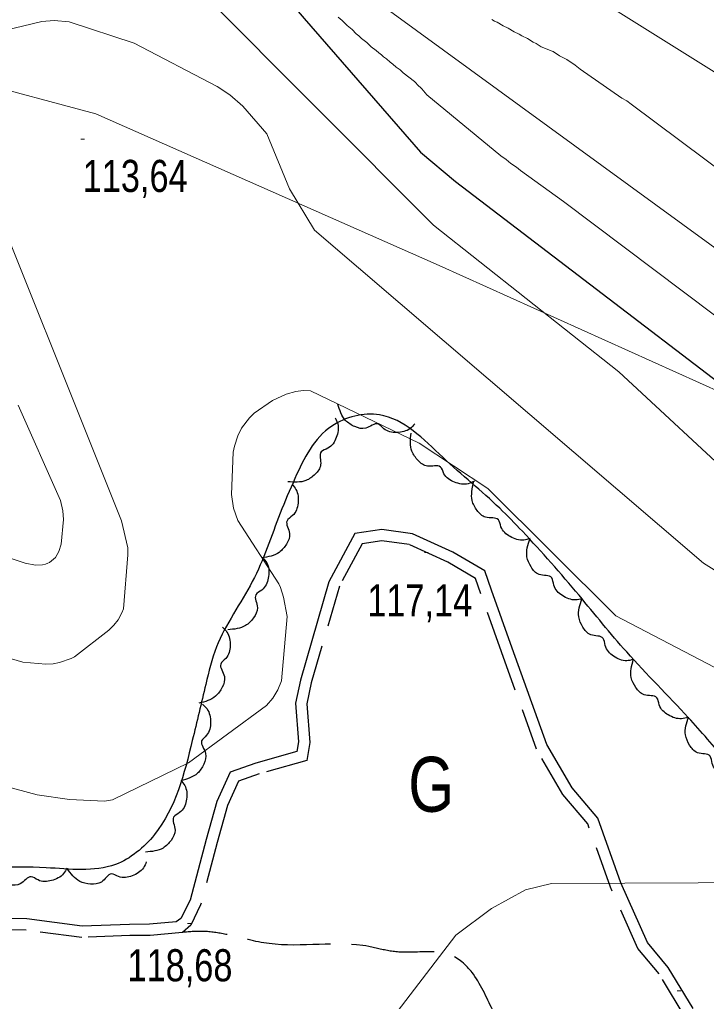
# Model space of a CAD drawing. Extents: x 483843 to 488449, y 4381269 to 4384483.
# Drawn here: x 485032.7 to 485220.1, y 4383169.1 to 4383436.9 of the extents above; entities that cross this region are included whole.
import ezdxf
from ezdxf.enums import TextEntityAlignment as Align

# ---------------------------------------------------------------- set-up
doc = ezdxf.new("R2010")
doc.units = 0
doc.header["$LTSCALE"] = 3.8
doc.linetypes.add('LONG_DASHED', pattern=[7.5, 6, -1.5])
doc.linetypes.add('MEDIUM_DASHED', pattern=[4.5, 3, -1.5])
for name, color, linetype, lineweight in [('15', 7, 'LONG_DASHED', 13), ('27', 7, 'Continuous', 25), ('38', 7, 'Continuous', 25), ('51', 7, 'Continuous', 13), ('7', 7, 'Continuous', 13), ('8', 7, 'Continuous', 25), ('9', 7, 'Continuous', 13)]:
    doc.layers.add(name, color=color, linetype=linetype, lineweight=lineweight)
doc.layers.add('31', color=7, linetype='Continuous')

msp = doc.modelspace()

# ---------------------------------------------------------------- linework, layer by layer
at = {"layer": '15'}
msp.add_spline([(485400.79, 4383245.56), (485366.79, 4383254.46), (485349.06, 4383265.95), (485335.06, 4383279.34), (485325.06, 4383291.04), (485319.26, 4383301.47), (485316.79, 4383311.82), (485317.67, 4383326.99), (485317.51, 4383342.72), (485315.45, 4383356.54), (485311.11, 4383375.24), (485304.67, 4383396.11), (485302.81, 4383413.58), (485295.88, 4383427.71), (485283.48, 4383443.67), (485274.41, 4383458.47), (485261.63, 4383473.96), (485248.35, 4383487.62), (485231.39, 4383496.46), (485206.95, 4383503.97), (485193.14, 4383504.9), (485172.81, 4383504.39), (485157.78, 4383504.12), (485145.67, 4383503.51), (485134.2, 4383504.43), (485123.74, 4383508.44), (485114.92, 4383511.93), (485112.2, 4383519.17), (485112.66, 4383528.99), (485114.36, 4383533.28), (485118.17, 4383541.74), (485121.31, 4383564.66), (485114.52, 4383595.67), (485109.69, 4383608.55), (485102.62, 4383619.36), (485089.28, 4383632.72), (485077.31, 4383638.83), (485057.92, 4383643.83), (485043.91, 4383643.5), (485030.6, 4383637.83), (485020.31, 4383630.47), (485011.46, 4383621.88), (484999.37, 4383601.37), (484981.13, 4383564.54), (484972.78, 4383546.81), (484964.72, 4383533.9), (484948.73, 4383515.05), (484938.85, 4383501.38), (484922.26, 4383484.64), (484903.34, 4383464.23), (484878.47, 4383440.05), (484853, 4383412.61), (484831.2, 4383387.67), (484805.14, 4383358.11), (484790.45, 4383334.7), (484768.3, 4383297.93), (484757.66, 4383281.26), (484749.41, 4383271.28), (484740.24, 4383261.88), (484732.92, 4383256.49), (484722.63, 4383254.85), (484718.27, 4383254.66), (484706.61, 4383259.28), (484700.75, 4383263.84), (484695.83, 4383273.7), (484694.44, 4383282.5), (484695.04, 4383297.06), (484696.68, 4383304.96), (484697.51, 4383309.13), (484702.36, 4383327.31), (484705.59, 4383338.26)], degree=3, dxfattribs=at)
at = {"layer": '27'}
for points in [[(485140.5, 4383326.6), (485139.25, 4383325.34), (485135.61, 4383324.28), (485132.06, 4383325.3), (485130.48, 4383326.61), (485127.12, 4383325.44), (485124.17, 4383325.88), (485121.64, 4383327.55), (485119.49, 4383332.01)], [(485368.83, 4383013.07), (485357.92, 4383017.58), (485339.7, 4383023.1), (485319.15, 4383029.84), (485302.76, 4383041.04), (485296.52, 4383049.17), (485289.67, 4383064.17), (485286.45, 4383083.98), (485285.97, 4383109.61), (485285.9, 4383115.54), (485276.33, 4383139.85), (485266.69, 4383152.65), (485256.52, 4383161.61), (485246.36, 4383180.33), (485238.82, 4383215.89), (485225.5, 4383234.69), (485215.14, 4383246.51), (485198.33, 4383264.41), (485185.34, 4383279.86), (485169.86, 4383297.33), (485163.7, 4383303.6), (485148.12, 4383317.53), (485130.86, 4383329.08), (485117.86, 4383326.04), (485107.82, 4383311.76), (485103.79, 4383302.24), (485096.18, 4383283.59), (485086.4, 4383265.77), (485083.47, 4383255.58), (485079.81, 4383240.29), (485069.46, 4383214.59), (485058.83, 4383206.45), (485039.94, 4383205.55), (485025.67, 4383205.73), (485007.1, 4383204.13), (484992.82, 4383195.6), (484980.34, 4383184.14), (484962.84, 4383175.41), (484943.61, 4383170.71), (484924.89, 4383162.35), (484905.09, 4383148.62), (484891.5, 4383130.5), (484881, 4383111.74), (484870.62, 4383107.18), (484861.85, 4383107.38), (484839.46, 4383112.83), (484820.21, 4383122.72), (484800.58, 4383135.19), (484785.62, 4383150.35), (484767.93, 4383154.78), (484745.46, 4383162.59)], [(485118.77, 4383328.3), (485119.47, 4383326.67), (485119.09, 4383322.89), (485116.81, 4383319.99), (485115.01, 4383319.01), (485114.83, 4383315.46), (485113.31, 4383312.89), (485110.82, 4383311.18), (485105.87, 4383310.85)], [(485156.77, 4383310.97), (485155.12, 4383310.3), (485151.35, 4383310.72), (485148.48, 4383313.04), (485147.52, 4383314.86), (485143.97, 4383315.08), (485141.43, 4383316.63), (485139.74, 4383319.14), (485139.48, 4383324.09)], [(485171.98, 4383295.4), (485170.26, 4383294.95), (485166.58, 4383295.87), (485164.03, 4383298.54), (485163.32, 4383300.47), (485159.84, 4383301.15), (485157.51, 4383303.03), (485156.17, 4383305.74), (485156.57, 4383310.68)], [(485107.01, 4383310.14), (485108.09, 4383308.73), (485108.65, 4383304.98), (485107.16, 4383301.6), (485105.65, 4383300.21), (485106.36, 4383296.72), (485105.52, 4383293.86), (485103.53, 4383291.58), (485098.81, 4383290.05)], [(485186.14, 4383278.95), (485184.4, 4383278.62), (485180.79, 4383279.79), (485178.44, 4383282.64), (485177.87, 4383284.62), (485174.44, 4383285.55), (485172.26, 4383287.59), (485171.12, 4383290.39), (485171.87, 4383295.29)], [(485099.35, 4383289.8), (485100.3, 4383288.31), (485100.55, 4383284.52), (485098.78, 4383281.29), (485097.16, 4383280.02), (485097.57, 4383276.49), (485096.49, 4383273.71), (485094.32, 4383271.6), (485089.49, 4383270.47)], [(485200.09, 4383262.33), (485198.34, 4383262.02), (485194.76, 4383263.26), (485192.46, 4383266.15), (485191.92, 4383268.13), (485188.51, 4383269.12), (485186.36, 4383271.2), (485185.26, 4383274.01), (485186.09, 4383278.91)], [(485088.07, 4383271.14), (485089.27, 4383269.82), (485090.15, 4383266.13), (485088.94, 4383262.64), (485087.56, 4383261.13), (485088.56, 4383257.71), (485087.96, 4383254.79), (485086.17, 4383252.35), (485081.6, 4383250.42)], [(485215.05, 4383246.6), (485213.32, 4383246.2), (485209.67, 4383247.23), (485207.21, 4383249.99), (485206.57, 4383251.93), (485203.1, 4383252.73), (485200.84, 4383254.68), (485199.58, 4383257.43), (485200.13, 4383262.35)], [(485082.59, 4383250.15), (485083.82, 4383248.87), (485084.8, 4383245.21), (485083.7, 4383241.69), (485082.35, 4383240.13), (485083.45, 4383236.75), (485082.93, 4383233.81), (485081.21, 4383231.32), (485076.69, 4383229.27)], [(485229.32, 4383230.26), (485227.58, 4383229.94), (485223.98, 4383231.14), (485221.65, 4383234.01), (485221.1, 4383235.98), (485217.67, 4383236.94), (485215.5, 4383238.99), (485214.38, 4383241.8), (485215.16, 4383246.69)], [(485076.98, 4383229.11), (485077.92, 4383227.6), (485078.15, 4383223.82), (485076.35, 4383220.59), (485074.72, 4383219.34), (485075.11, 4383215.8), (485074.01, 4383213.03), (485071.83, 4383210.94), (485066.99, 4383209.84)], [(485067.25, 4383207.15), (485066.48, 4383205.55), (485063.39, 4383203.35), (485059.7, 4383203.15), (485057.77, 4383203.86), (485054.99, 4383201.66), (485052.05, 4383201.11), (485049.12, 4383201.85), (485045.62, 4383205.37)], [(485045.61, 4383205.47), (485044.69, 4383203.96), (485041.4, 4383202.06), (485037.71, 4383202.22), (485035.87, 4383203.11), (485032.88, 4383201.18), (485029.91, 4383200.92), (485027.06, 4383201.94), (485023.91, 4383205.77)]]:
    msp.add_spline(points, degree=3, dxfattribs=at)
at = {"layer": '38'}
msp.add_lwpolyline([(485216.43, 4383167.19), (485209.65, 4383178.39), (485204.03, 4383185.2), (485196.72, 4383201.4), (485190.43, 4383219.04), (485183.46, 4383227.33), (485176.52, 4383239.18), (485167.04, 4383265.48), (485161.4, 4383281.26), (485159.63, 4383286.5), (485150.93, 4383291.65), (485139.86, 4383296.67), (485131.54, 4383297.79), (485124.15, 4383296.71), (485117.08, 4383283.56), (485109.29, 4383256.75), (485108, 4383250.47), (485108.8, 4383239.89), (485108.34, 4383237.22), (485097.1, 4383234.07), (485090.13, 4383231.62), (485086.54, 4383223.64), (485083.6, 4383213.26), (485079.22, 4383196.7), (485076.69, 4383191.73), (485075.36, 4383190.85), (485068.14, 4383190.15), (485062.71, 4383190.12), (485049.77, 4383189.63), (485034.7, 4383191.59), (485018.14, 4383192.03)], dxfattribs=at)
at = {"layer": '38', "linetype": 'MEDIUM_DASHED'}
msp.add_lwpolyline([(485214, 4383165.29), (485207.15, 4383176.62), (485201.4, 4383183.57), (485193.88, 4383200.26), (485187.73, 4383217.5), (485180.95, 4383225.56), (485173.73, 4383237.88), (485164.16, 4383264.45), (485158.5, 4383280.26), (485157.09, 4383284.44), (485149.51, 4383288.93), (485139, 4383293.7), (485131.56, 4383294.69), (485126.12, 4383293.9), (485119.94, 4383282.39), (485112.26, 4383256.01), (485111.09, 4383250.27), (485111.88, 4383239.75), (485111.03, 4383234.79), (485098.03, 4383231.14), (485092.39, 4383229.16), (485089.43, 4383222.58), (485086.56, 4383212.45), (485082.05, 4383195.43), (485079.37, 4383189.86), (485077.12, 4383187.94), (485068.3, 4383187.09), (485062.78, 4383187.06), (485049.63, 4383186.56), (485034.46, 4383188.53), (485018.55, 4383188.96)], dxfattribs=at)
at = {"layer": '38', "linetype": 'LONG_DASHED'}
msp.add_spline([(485200.63, 4383002.8), (485199.67, 4383016.63), (485199.56, 4383027.1), (485196.85, 4383042.11), (485198.01, 4383051.44), (485201.06, 4383058.64), (485203.47, 4383067.09), (485202.11, 4383076.81), (485195.91, 4383089.08), (485190.65, 4383096.14), (485184.34, 4383102.73), (485183.55, 4383105.45), (485179.05, 4383120.84), (485177.29, 4383127.03), (485173.4, 4383135.76), (485169.45, 4383148.01), (485167.35, 4383156.29), (485162.13, 4383166.09), (485156.49, 4383176.54), (485150.46, 4383181.66), (485140.64, 4383182.55), (485134.19, 4383182.78), (485127.99, 4383184.07), (485100.75, 4383184.86), (485089.34, 4383187.3), (485083.17, 4383188.19), (485077.12, 4383187.94)], degree=3, dxfattribs=at)
at = {"layer": '51'}
msp.add_lwpolyline([(485400.13, 4383207.61), (485339.93, 4383235.81), (485304.61, 4383259.5), (485273.66, 4383308.81), (485237.83, 4383336.45), (485231.15, 4383332), (485147.19, 4383369.84), (485053.5, 4383411.23), (485019.48, 4383420.27), (484981.87, 4383400.27), (484953.62, 4383385.83), (484933.81, 4383374.86), (484903, 4383358.06), (484866.78, 4383335.14), (484831.69, 4383306.08), (484808.69, 4383288.72)], dxfattribs=at)
at = {"layer": '7'}
for p, q in [((485049.4, 4383404.25), (485050.4, 4383404.25)), ((485143.14, 4383291.54), (485144.14, 4383291.54)), ((485078.5, 4383190.37), (485079.5, 4383190.37)), ((485212.06, 4383171.99), (485213.06, 4383171.99))]:
    msp.add_line(p, q, dxfattribs=at)
at = {"layer": '8'}
msp.add_lwpolyline([(485018.99, 4383472.09), (485036.33, 4383476.56), (485043.7, 4383477.38), (485053.15, 4383476.99), (485060.48, 4383475.58), (485066.79, 4383473.29), (485074.04, 4383469.36), (485104.21, 4383444.35), (485110.35, 4383437.17), (485142.04, 4383400.71), (485151.6, 4383392.73), (485263.55, 4383307.27), (485270.76, 4383300.01), (485272.68, 4383296.91), (485279.59, 4383279.09), (485284.56, 4383269.99), (485307.74, 4383236.62), (485311.19, 4383233.15), (485312.03, 4383232.62), (485312.19, 4383232.54), (485312.73, 4383232.36), (485313.52, 4383231.99), (485406.85, 4383183.29)], dxfattribs=at)
at = {"layer": '9'}
for points in [[(485081.86, 4383526.22), (485081.96, 4383522.06), (485081.59, 4383516.54), (485082.19, 4383511.75), (485085.29, 4383503.67), (485085.88, 4383502.53), (485101.79, 4383485.13), (485110.31, 4383478.5), (485135.05, 4383464.65), (485191.62, 4383441.71), (485223.65, 4383421.69), (485286.39, 4383360.36), (485299.05, 4383337.09), (485299.92, 4383333.73), (485299.93, 4383305.9), (485302.9, 4383296.33), (485327.9, 4383259.15), (485335.42, 4383251.3), (485340.66, 4383247.14), (485378.3, 4383230.37), (485385.86, 4383228.3), (485411.55, 4383226.12)], [(485018.37, 4383498.06), (485038.34, 4383510.14), (485043.74, 4383512.22), (485047.67, 4383513.14), (485055.93, 4383513.36), (485058.8, 4383512.98), (485059.45, 4383512.81), (485062.98, 4383511.22), (485066.16, 4383509.1), (485068.88, 4383506.47), (485069.43, 4383505.81), (485090.99, 4383474.57), (485104.12, 4383460.83), (485228.34, 4383370.23)], [(485279.36, 4383268.1), (485266.91, 4383288.59), (485264.97, 4383290.52), (485230.14, 4383309.36), (485196.16, 4383340.78), (485145.66, 4383380.84), (485082.4, 4383444.24), (485081.24, 4383444.97), (485075.94, 4383447.53), (485048.38, 4383456.65), (485041.87, 4383457.53), (485030.37, 4383457.57)], [(485028.54, 4383433.92), (485038.74, 4383436.41), (485042.12, 4383436.66), (485046.22, 4383436.28), (485063.98, 4383430.44), (485086.61, 4383418.61), (485090.03, 4383416.4), (485093.58, 4383413.27), (485100.1, 4383405.74), (485106.34, 4383390.76), (485113.18, 4383379.43), (485219.33, 4383288.62), (485225.37, 4383284.78)], [(485119.57, 4383437.58), (485120.74, 4383436.67), (485122.05, 4383435.29), (485123.38, 4383434.22), (485124.54, 4383433.02), (485125.28, 4383432.42), (485125.96, 4383431.77), (485127.41, 4383430.64), (485128.57, 4383429.48), (485130.01, 4383428.45), (485130.71, 4383427.8), (485131.4, 4383427.31), (485132.02, 4383426.73), (485132.78, 4383426.17), (485133.76, 4383425.26)], [(485161.49, 4383436.93), (485162.3, 4383436.47), (485162.99, 4383436.17), (485164.6, 4383435.18), (485166.02, 4383434.54), (485167.59, 4383433.53), (485169.03, 4383432.88), (485169.71, 4383432.45), (485171.31, 4383431.74), (485172.81, 4383430.76), (485173.66, 4383430.34), (485175, 4383429.48), (485178.03, 4383428.27), (485178.27, 4383428.15), (485179.97, 4383427.03), (485181.99, 4383426.05), (485184.31, 4383424.45), (485185.61, 4383423.34), (485197.04, 4383415.48), (485198.35, 4383414.7), (485199.51, 4383413.84), (485233.3, 4383388.68)], [(485133.76, 4383425.26), (485134.51, 4383424.71), (485135.42, 4383423.92), (485136.49, 4383423.19), (485136.59, 4383423.1), (485137.35, 4383422.36), (485140.43, 4383420.02), (485140.87, 4383419.57), (485141.15, 4383419.22), (485142.45, 4383418.04), (485143.8, 4383416.36), (485163.97, 4383399.76), (485165.43, 4383398.77), (485166.76, 4383397.66), (485168.23, 4383396.68), (485169.4, 4383395.73), (485181.09, 4383387.25), (485222.29, 4383356.25)], [(485030.45, 4383262.51), (485033.59, 4383261.66), (485039.86, 4383261.06), (485041.87, 4383261.15), (485043.58, 4383261.5), (485046.74, 4383262.62), (485047.66, 4383263.07), (485057.04, 4383270.33), (485058.41, 4383271.68), (485059.57, 4383273.18), (485060.59, 4383275.07), (485061.01, 4383276.15), (485062.24, 4383290.88), (485062.22, 4383292.78), (485060.46, 4383300.15), (485018.86, 4383404)], [(485104.72, 4383279.32), (485103.84, 4383282.04), (485103.44, 4383282.98), (485092.25, 4383300.28), (485091.04, 4383303.59), (485090.47, 4383307.32), (485091, 4383318.89), (485091.29, 4383320.54), (485092.26, 4383323.38), (485093.25, 4383325.42), (485095.37, 4383328.23), (485096.69, 4383329.56), (485101.72, 4383333.02), (485105.39, 4383334.75), (485108.02, 4383335.48), (485110.01, 4383335.77), (485112.06, 4383335.63), (485141.73, 4383321.38), (485160.46, 4383309), (485195.4, 4383274.28), (485263.86, 4383238.55), (485329.43, 4383192.48), (485339.13, 4383184.24), (485355.63, 4383162.95)], [(485032.32, 4383331.74), (485043.84, 4383305.72), (485044.46, 4383302.89), (485044.67, 4383300.57), (485044.06, 4383293.81), (485043.42, 4383291.83), (485042.51, 4383290.19), (485040.81, 4383288.85), (485040.42, 4383288.63), (485039.75, 4383288.37), (485038.92, 4383288.15), (485037.03, 4383288.12), (485034.16, 4383288.64), (485029.85, 4383290.09)], [(484991.92, 4383237.73), (485037.51, 4383225.48), (485046.34, 4383224.17), (485055.85, 4383223.69), (485058.01, 4383224.04), (485078.8, 4383234.13), (485100.02, 4383249.79), (485101.75, 4383251.83), (485103.13, 4383254.11), (485104.13, 4383256.56), (485105.67, 4383274.11), (485104.72, 4383279.32)], [(485132.39, 4383161.96), (485151.72, 4383187.14), (485161.41, 4383194.44), (485170.71, 4383199.57), (485177.85, 4383201.27), (485257.89, 4383201.67), (485268.17, 4383199.49), (485283.39, 4383193.7), (485287.68, 4383191.5), (485316.17, 4383168.07)]]:
    msp.add_lwpolyline(points, dxfattribs=at)

# ---------------------------------------------------------------- texts
at = {"layer": '31', "width": 0.8}
msp.add_text('G', height=15, dxfattribs=at).set_placement((485144.98, 4383220.82), align=Align.CENTER)
at = {"layer": '7', "width": 0.8}
for s, p in [('113,64', (485049.9, 4383389.88)), ('117,14', (485127.54, 4383274.1)), ('118,68', (485062.13, 4383174.59))]:
    msp.add_text(s, height=8.75, dxfattribs=at).set_placement(p)

doc.saveas('drawing.dxf')
